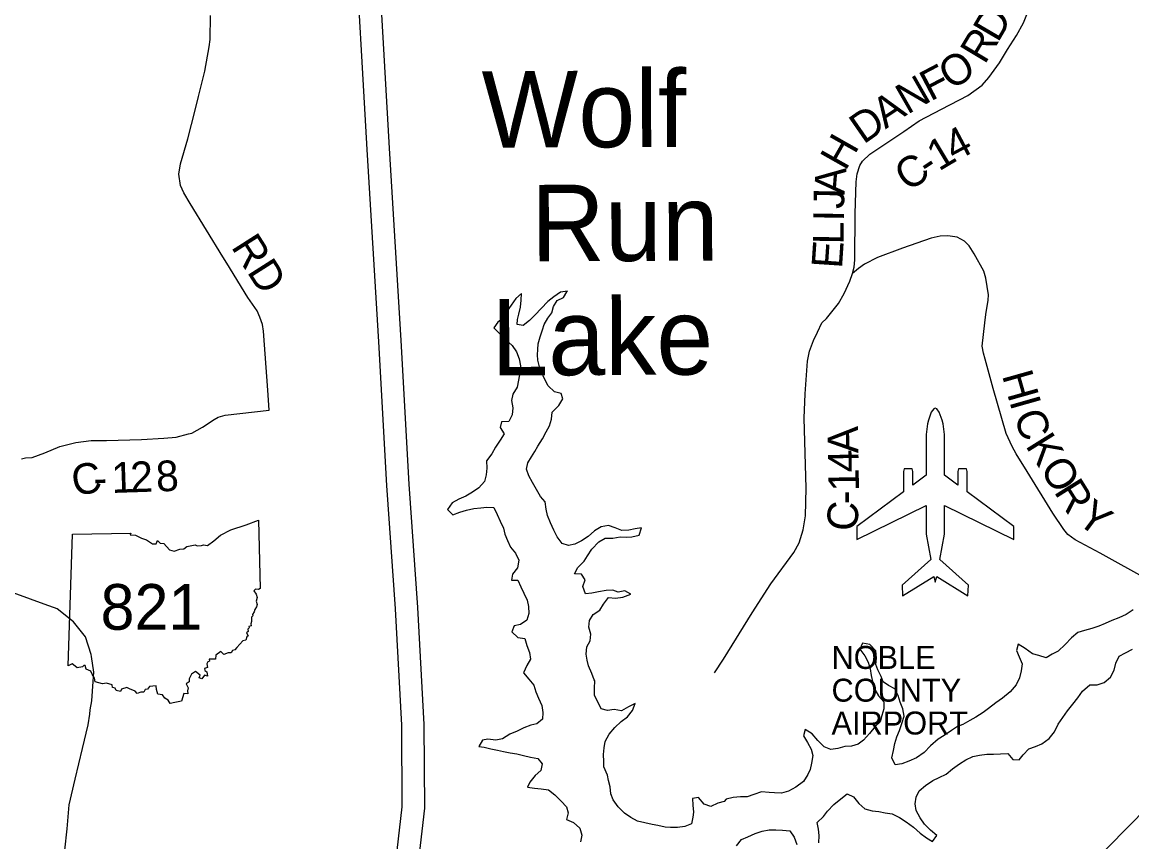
# Model space of a CAD drawing. Extents: x -452339 to 6403467, y -1 to 1814750.
# Drawn here: x -60980 to -50105, y 1606675 to 1614709 of the extents above; entities that cross this region are included whole.
import ezdxf

# ---------------------------------------------------------------- set-up
doc = ezdxf.new("R2010")
doc.units = 0
for name, color, linetype in [('Default', 7, 'Continuous'), ('GM_X_Adjacent_County_Text', 7, 'Continuous'), ('GM_X_County', 7, 'Continuous'), ('GM_X_County_Road', 7, 'Continuous'), ('GM_X_Minor_Lake_Text', 7, 'Continuous')]:
    doc.layers.add(name, color=color, linetype=linetype)

msp = doc.modelspace()

# ---------------------------------------------------------------- linework, layer by layer
at = {"layer": 'Default'}
msp.add_line((-60528, 1608400), (-60486, 1609691), dxfattribs=at)
for points in [[(-58975, 1612346), (-59013, 1612409), (-59335, 1612931), (-59395, 1613037), (-59427, 1613109), (-59443, 1613218), (-59427, 1613320), (-59356, 1613566), (-59285, 1613847), (-59252, 1613979), (-59190, 1614228), (-59147, 1614466), (-59139, 1614540), (-59135, 1614773)], [(-52843, 1612244), (-52825, 1612306), (-52819, 1612378), (-52817, 1612833), (-52808, 1613145), (-52796, 1613221), (-52770, 1613304), (-52744, 1613348), (-52672, 1613416), (-52340, 1613637), (-52188, 1613743), (-51971, 1613856), (-51713, 1613990), (-51573, 1614091), (-51505, 1614165), (-51401, 1614310), (-51325, 1614440), (-51235, 1614578), (-51168, 1614701), (-51134, 1614783)], [(-49939, 1609241), (-50417, 1609504), (-50659, 1609634), (-50733, 1609688), (-50773, 1609736), (-50879, 1609898), (-51131, 1610305), (-51237, 1610479), (-51279, 1610551), (-51338, 1610677), (-51464, 1611118), (-51542, 1611406), (-51558, 1611464), (-51572, 1611534), (-51547, 1611763), (-51537, 1611843), (-51513, 1611983), (-51509, 1612035), (-51535, 1612201), (-51557, 1612268), (-51649, 1612438), (-51699, 1612518), (-51745, 1612562), (-51817, 1612602), (-51907, 1612616), (-51985, 1612612), (-52073, 1612593), (-52351, 1612495), (-52599, 1612402), (-52725, 1612336), (-52783, 1612294), (-52843, 1612244)], [(-58560, 1610905), (-58572, 1611101), (-58616, 1611680), (-58626, 1611746), (-58652, 1611818), (-58678, 1611880), (-58768, 1612011), (-58975, 1612346)], [(-54196, 1608333), (-54107, 1608466), (-53827, 1608919), (-53643, 1609203), (-53418, 1609510), (-53366, 1609606), (-53326, 1609733), (-53302, 1609869), (-53298, 1610143), (-53317, 1610828), (-53307, 1611067), (-53284, 1611387), (-53264, 1611484), (-53224, 1611588), (-53184, 1611672), (-53142, 1611762), (-53098, 1611804), (-53044, 1611871), (-52980, 1611951), (-52924, 1612049), (-52869, 1612171), (-52843, 1612244)], [(-60986, 1610429), (-60946, 1610439), (-60882, 1610443), (-60758, 1610489), (-60611, 1610549), (-60453, 1610590), (-60305, 1610608), (-60155, 1610608), (-59809, 1610617), (-59591, 1610631), (-59471, 1610643), (-59351, 1610673), (-59318, 1610680), (-59213, 1610740), (-59099, 1610814), (-59059, 1610836), (-58989, 1610858), (-58560, 1610905)], [(-60486, 1609691), (-59914, 1609700), (-59922, 1609684), (-59869, 1609681), (-59811, 1609653), (-59763, 1609636), (-59704, 1609595), (-59668, 1609595), (-59653, 1609629), (-59626, 1609603), (-59593, 1609598), (-59537, 1609536), (-59491, 1609523), (-59436, 1609544), (-59395, 1609548), (-59365, 1609569), (-59286, 1609587), (-59264, 1609576), (-59223, 1609578), (-59202, 1609586), (-59165, 1609579), (-59102, 1609626), (-59036, 1609681), (-58935, 1609734), (-58784, 1609783), (-58664, 1609827), (-58647, 1609157)], [(-60663, 1608968), (-60729, 1608992), (-61068, 1609116)], [(-58647, 1609157), (-58665, 1609148), (-58692, 1609152), (-58711, 1609134), (-58688, 1609102), (-58677, 1609069), (-58687, 1609033), (-58677, 1609002), (-58683, 1608977), (-58701, 1608952), (-58707, 1608928), (-58721, 1608903), (-58720, 1608889), (-58734, 1608878), (-58732, 1608836), (-58739, 1608813), (-58736, 1608793), (-58759, 1608787), (-58754, 1608771), (-58768, 1608758), (-58765, 1608736), (-58782, 1608722), (-58766, 1608694), (-58778, 1608685), (-58789, 1608651), (-58818, 1608644), (-58876, 1608581), (-58897, 1608558), (-58920, 1608552), (-58933, 1608527), (-58961, 1608527), (-59004, 1608511), (-59032, 1608539), (-59081, 1608505), (-59086, 1608464), (-59147, 1608466), (-59145, 1608445), (-59159, 1608439), (-59171, 1608419), (-59164, 1608383), (-59193, 1608373), (-59190, 1608353), (-59171, 1608340), (-59163, 1608300), (-59194, 1608308), (-59218, 1608274), (-59245, 1608282), (-59236, 1608310), (-59280, 1608345), (-59321, 1608317), (-59342, 1608273), (-59343, 1608243), (-59374, 1608225), (-59354, 1608183), (-59358, 1608154), (-59357, 1608127), (-59395, 1608128), (-59419, 1608054)], [(-60318, 1607927), (-60312, 1607968), (-60298, 1608057), (-60283, 1608245), (-60279, 1608337), (-60301, 1608491), (-60304, 1608512), (-60359, 1608686), (-60478, 1608832), (-60638, 1608959), (-60663, 1608968)], [(-50092, 1608948), (-50162, 1608903), (-50231, 1608872), (-50301, 1608845), (-50365, 1608815), (-50428, 1608790), (-50498, 1608767), (-50568, 1608746), (-50634, 1608728), (-50697, 1608675), (-50760, 1608610), (-50826, 1608545), (-50887, 1608515), (-50945, 1608478), (-51015, 1608501), (-51079, 1608519), (-51150, 1608570), (-51218, 1608611), (-51236, 1608549), (-51209, 1608487), (-51180, 1608421), (-51190, 1608351), (-51207, 1608281), (-51238, 1608213), (-51299, 1608146), (-51371, 1608083), (-51438, 1608038), (-51510, 1607981), (-51561, 1607943), (-51635, 1607896), (-51694, 1607863), (-51762, 1607826), (-51814, 1607804), (-51871, 1607767), (-51945, 1607716), (-52002, 1607680), (-52078, 1607615), (-52139, 1607552), (-52216, 1607499), (-52290, 1607466), (-52360, 1607438), (-52424, 1607431), (-52456, 1607499), (-52441, 1607571), (-52428, 1607639), (-52409, 1607705), (-52383, 1607766), (-52358, 1607836), (-52335, 1607906)], [(-59419, 1608054), (-59485, 1608040), (-59531, 1608031), (-59548, 1608065), (-59581, 1608083), (-59603, 1608116), (-59650, 1608121), (-59662, 1608168), (-59667, 1608205), (-59732, 1608196), (-59750, 1608173), (-59773, 1608167), (-59786, 1608143), (-59818, 1608142), (-59852, 1608130), (-59874, 1608153), (-59929, 1608176), (-59954, 1608188), (-60006, 1608170), (-60017, 1608148), (-60058, 1608158), (-60068, 1608182), (-60093, 1608189), (-60099, 1608215), (-60152, 1608229), (-60194, 1608223), (-60266, 1608244), (-60270, 1608278), (-60295, 1608319), (-60307, 1608348), (-60353, 1608369), (-60362, 1608403), (-60377, 1608402), (-60390, 1608389), (-60441, 1608382), (-60461, 1608396), (-60490, 1608420), (-60528, 1608400)], [(-60573, 1606300), (-60561, 1606593), (-60538, 1606802), (-60519, 1607037), (-60460, 1607290), (-60389, 1607589), (-60333, 1607822), (-60318, 1607927)], [(-56900, 1601787), (-56832, 1601823), (-56536, 1601971), (-56496, 1601992), (-56117, 1602200), (-55807, 1602369), (-55583, 1602550), (-54899, 1603355), (-54089, 1604287), (-53837, 1604520), (-53472, 1604763), (-53184, 1604921), (-53155, 1604931), (-52573, 1605151), (-52123, 1605283), (-51847, 1605384), (-51593, 1605470), (-51435, 1605571), (-50876, 1606075), (-50152, 1606812), (-49304, 1607670)]]:
    msp.add_lwpolyline(points, dxfattribs=at)
msp.add_lwpolyline([(-52344, 1610104), (-52800, 1609767), (-52800, 1609637), (-52121, 1609972), (-52121, 1609690), (-52076, 1609441), (-52355, 1609190), (-52351, 1609087), (-52045, 1609277), (-52031, 1609221), (-52017, 1609277), (-51711, 1609087), (-51706, 1609190), (-51986, 1609441), (-51941, 1609690), (-51941, 1609972), (-51262, 1609637), (-51262, 1609767), (-51718, 1610104), (-51718, 1610306), (-51725, 1610330), (-51803, 1610330), (-51810, 1610306), (-51810, 1610172), (-51941, 1610269), (-51941, 1610269), (-51941, 1610667), (-51954, 1610772), (-51965, 1610809), (-51992, 1610886), (-52016, 1610920), (-52031, 1610926), (-52045, 1610920), (-52070, 1610886), (-52097, 1610809), (-52108, 1610772), (-52121, 1610667), (-52121, 1610269), (-52252, 1610172), (-52252, 1610306), (-52259, 1610330), (-52336, 1610330), (-52344, 1610306)], close=True, dxfattribs=at)
at = {"layer": 'GM_X_County_Road'}
for points in [[(-58024, 1603953), (-57930, 1604177), (-57705, 1604759), (-57647, 1604920), (-57363, 1605645), (-57337, 1605728), (-57219, 1606057), (-57156, 1606262), (-57087, 1606553), (-57035, 1607005), (-57040, 1607824), (-57101, 1608973), (-57187, 1610182), (-57265, 1611589), (-57379, 1613474), (-57506, 1615703)], [(-58227, 1604038), (-58134, 1604259), (-57911, 1604836), (-57853, 1604997), (-57571, 1605717), (-57546, 1605798), (-57428, 1606127), (-57368, 1606320), (-57304, 1606591), (-57255, 1607017), (-57260, 1607818), (-57320, 1608959), (-57407, 1610168), (-57485, 1611576), (-57598, 1613461), (-57725, 1615691)]]:
    msp.add_lwpolyline(points, dxfattribs=at)
at = {"layer": 'GM_X_Minor_Lake_Text'}
for points in [[(-55637, 1612072), (-55704, 1612061), (-55768, 1612016), (-55829, 1611971), (-55895, 1611903), (-55952, 1611842), (-56009, 1611785), (-56069, 1611736), (-56129, 1611746), (-56124, 1611796), (-56114, 1611846), (-56097, 1611914), (-56091, 1611983), (-56088, 1612049), (-56142, 1612000), (-56189, 1611935), (-56228, 1611881), (-56256, 1611813), (-56319, 1611770), (-56359, 1611713), (-56239, 1611596), (-56179, 1611541), (-56134, 1611477), (-56110, 1611410), (-56097, 1611342), (-56104, 1611273), (-56117, 1611201), (-56129, 1611133), (-56172, 1611064), (-56185, 1611000), (-56171, 1610930), (-56178, 1610860), (-56211, 1610794), (-56283, 1610791), (-56295, 1610735), (-56256, 1610675), (-56297, 1610611), (-56341, 1610544), (-56378, 1610479), (-56431, 1610411), (-56426, 1610339), (-56432, 1610271), (-56449, 1610206), (-56506, 1610144), (-56566, 1610101), (-56633, 1610062), (-56701, 1610033), (-56765, 1609999), (-56810, 1609934), (-56758, 1609881), (-56690, 1609905), (-56624, 1609926), (-56554, 1609943), (-56486, 1609948), (-56426, 1609956), (-56358, 1609951), (-56324, 1609883), (-56295, 1609818), (-56264, 1609748), (-56250, 1609692), (-56225, 1609628), (-56194, 1609562), (-56144, 1609505), (-56113, 1609437), (-56124, 1609361), (-56174, 1609298), (-56183, 1609240), (-56123, 1609239), (-56092, 1609175), (-56064, 1609111), (-56031, 1609044), (-56019, 1608982), (-56016, 1608914), (-56035, 1608847), (-56097, 1608805), (-56158, 1608792), (-56182, 1608732), (-56121, 1608678), (-56053, 1608667), (-56033, 1608599), (-56008, 1608531), (-55997, 1608465), (-56033, 1608403), (-56066, 1608330), (-56013, 1608269), (-55965, 1608211), (-55946, 1608145), (-55921, 1608082), (-55887, 1608012), (-55878, 1607942), (-55881, 1607878), (-55935, 1607831), (-55994, 1607817), (-56062, 1607792), (-56128, 1607759), (-56200, 1607732), (-56273, 1607685), (-56337, 1607671), (-56415, 1607680), (-56467, 1607671), (-56506, 1607611)], [(-55369, 1608252), (-55375, 1608262), (-55396, 1608326), (-55429, 1608399), (-55443, 1608455), (-55454, 1608515), (-55445, 1608585), (-55413, 1608646), (-55408, 1608712), (-55425, 1608778), (-55419, 1608844), (-55384, 1608904), (-55320, 1608945), (-55283, 1609006), (-55234, 1609070), (-55164, 1609063), (-55094, 1609072), (-55014, 1609101), (-55074, 1609134), (-55140, 1609121), (-55190, 1609141), (-55258, 1609138), (-55332, 1609127), (-55398, 1609112), (-55460, 1609106), (-55485, 1609178), (-55463, 1609244), (-55498, 1609298), (-55566, 1609301), (-55533, 1609365), (-55473, 1609426), (-55440, 1609478), (-55398, 1609543), (-55329, 1609614), (-55266, 1609653), (-55192, 1609653), (-55120, 1609664), (-55056, 1609661), (-55004, 1609663), (-54932, 1609682), (-54911, 1609753), (-54973, 1609742), (-55033, 1609731), (-55102, 1609728), (-55169, 1609754), (-55233, 1609775), (-55307, 1609762), (-55370, 1609724), (-55434, 1609669), (-55499, 1609626), (-55563, 1609593), (-55627, 1609581), (-55687, 1609600), (-55738, 1609665), (-55770, 1609729), (-55803, 1609801), (-55830, 1609875), (-55846, 1609937), (-55855, 1610009), (-55900, 1610060), (-55938, 1610128), (-55979, 1610197), (-56016, 1610263), (-56036, 1610329), (-56025, 1610391), (-55990, 1610448), (-55956, 1610500), (-55927, 1610552), (-55880, 1610625), (-55844, 1610694), (-55811, 1610754), (-55794, 1610818), (-55786, 1610886), (-55719, 1610951), (-55682, 1611016), (-55698, 1611070), (-55764, 1611087), (-55825, 1611144), (-55862, 1611212), (-55890, 1611278), (-55911, 1611332), (-55925, 1611396), (-55928, 1611448), (-55927, 1611500), (-55923, 1611556), (-55904, 1611624), (-55879, 1611692), (-55865, 1611745), (-55828, 1611809), (-55788, 1611860), (-55773, 1611922), (-55738, 1611980), (-55674, 1612011), (-55642, 1612066), (-55637, 1612072)], [(-50092, 1608948), (-50162, 1608903), (-50231, 1608872), (-50301, 1608845), (-50365, 1608815), (-50428, 1608790), (-50498, 1608767), (-50568, 1608746), (-50634, 1608728), (-50697, 1608675), (-50760, 1608610), (-50826, 1608545), (-50887, 1608515), (-50945, 1608478), (-51015, 1608501), (-51079, 1608519), (-51150, 1608570), (-51218, 1608611), (-51236, 1608549), (-51209, 1608487), (-51180, 1608421), (-51190, 1608351), (-51207, 1608281), (-51238, 1608213), (-51299, 1608146), (-51371, 1608083), (-51438, 1608038), (-51510, 1607981), (-51561, 1607943), (-51635, 1607896), (-51694, 1607863), (-51762, 1607826), (-51814, 1607804), (-51871, 1607767), (-51945, 1607716), (-52002, 1607680), (-52078, 1607615), (-52139, 1607552), (-52216, 1607499), (-52290, 1607466), (-52360, 1607438), (-52424, 1607431), (-52456, 1607499), (-52441, 1607571), (-52428, 1607639), (-52409, 1607705), (-52383, 1607766), (-52358, 1607836), (-52335, 1607906)], [(-52335, 1607906), (-52349, 1607978), (-52376, 1608044), (-52395, 1608108), (-52429, 1608174), (-52490, 1608209), (-52542, 1608244), (-52561, 1608296), (-52595, 1608360), (-52614, 1608414), (-52606, 1608474), (-52613, 1608546), (-52672, 1608609), (-52744, 1608623), (-52771, 1608564), (-52723, 1608497), (-52690, 1608435), (-52671, 1608371), (-52659, 1608305), (-52644, 1608235), (-52625, 1608167), (-52587, 1608106), (-52534, 1608046), (-52537, 1607980), (-52555, 1607912), (-52570, 1607850), (-52621, 1607805), (-52675, 1607738), (-52734, 1607670), (-52786, 1607631), (-52851, 1607612), (-52917, 1607608), (-52987, 1607591), (-53055, 1607580), (-53121, 1607606), (-53182, 1607669), (-53239, 1607734), (-53307, 1607776), (-53324, 1607713), (-53284, 1607648), (-53249, 1607584), (-53230, 1607520), (-53246, 1607446), (-53259, 1607384), (-53280, 1607334), (-53322, 1607265), (-53397, 1607210), (-53469, 1607173), (-53540, 1607153), (-53608, 1607154), (-53660, 1607159), (-53733, 1607166), (-53810, 1607138), (-53874, 1607115), (-53940, 1607116), (-54012, 1607111), (-54080, 1607093)], [(-53172, 1606666), (-53168, 1606738), (-53177, 1606798), (-53188, 1606866), (-53126, 1606925), (-53089, 1606975), (-53025, 1607040), (-52956, 1607097), (-52895, 1607145), (-52832, 1607116), (-52782, 1607051), (-52723, 1606999), (-52651, 1606980), (-52585, 1606973), (-52523, 1606959), (-52453, 1606948), (-52382, 1606915), (-52316, 1606871), (-52245, 1606820), (-52181, 1606761), (-52118, 1606713), (-52058, 1606680), (-52017, 1606737), (-52079, 1606788), (-52136, 1606847), (-52180, 1606911), (-52219, 1606981), (-52230, 1607049), (-52218, 1607113), (-52189, 1607175), (-52126, 1607228), (-52056, 1607275), (-51993, 1607305), (-51925, 1607338), (-51861, 1607389), (-51794, 1607438), (-51732, 1607478), (-51663, 1607511), (-51599, 1607524), (-51527, 1607533), (-51461, 1607535), (-51391, 1607538), (-51319, 1607541), (-51271, 1607483), (-51209, 1607478), (-51169, 1607529), (-51116, 1607587), (-51050, 1607610), (-50988, 1607637), (-50915, 1607688), (-50864, 1607754), (-50826, 1607827), (-50781, 1607895), (-50736, 1607958), (-50684, 1608024), (-50635, 1608085), (-50590, 1608152), (-50518, 1608214), (-50446, 1608215), (-50375, 1608238), (-50315, 1608289), (-50278, 1608359), (-50261, 1608427), (-50229, 1608496), (-50168, 1608529), (-50098, 1608563)], [(-54080, 1607093), (-54101, 1607072), (-54161, 1607054), (-54231, 1607021), (-54295, 1607044), (-54352, 1607108), (-54412, 1607101), (-54407, 1607033), (-54402, 1606967), (-54406, 1606917), (-54421, 1606853), (-54485, 1606826), (-54557, 1606815), (-54625, 1606816), (-54679, 1606820), (-54751, 1606835), (-54805, 1606846), (-54879, 1606860), (-54949, 1606877), (-55014, 1606914), (-55078, 1606956), (-55139, 1607019), (-55187, 1607087), (-55212, 1607146), (-55219, 1607214), (-55233, 1607276), (-55244, 1607330), (-55279, 1607410), (-55279, 1607464), (-55282, 1607532), (-55276, 1607596), (-55267, 1607660), (-55228, 1607729), (-55173, 1607795), (-55109, 1607856), (-55048, 1607901), (-55000, 1607962), (-54971, 1608030), (-55039, 1607997), (-55108, 1607960), (-55178, 1607972), (-55242, 1607963), (-55306, 1607978), (-55339, 1608046), (-55372, 1608110), (-55372, 1608180), (-55369, 1608252)], [(-56506, 1607611), (-56452, 1607603), (-56386, 1607588), (-56322, 1607573), (-56262, 1607561), (-56198, 1607546), (-56132, 1607539), (-56067, 1607521), (-55997, 1607506), (-55925, 1607493), (-55883, 1607441), (-55898, 1607375), (-55953, 1607325), (-56005, 1607260), (-56026, 1607210), (-55958, 1607202), (-55894, 1607193), (-55822, 1607184), (-55760, 1607136), (-55697, 1607075), (-55644, 1607018), (-55630, 1606958), (-55647, 1606895), (-55577, 1606866), (-55516, 1606809), (-55494, 1606741), (-55509, 1606675)], [(-53981, 1606637), (-53932, 1606698), (-53868, 1606723), (-53798, 1606757), (-53729, 1606780), (-53659, 1606793), (-53595, 1606794), (-53527, 1606790), (-53457, 1606783), (-53414, 1606721), (-53387, 1606648)]]:
    msp.add_lwpolyline(points, dxfattribs=at)

# ---------------------------------------------------------------- texts
at = {"layer": 'Default'}
msp.add_text('821', height=447.7, dxfattribs=at).set_placement((-60212, 1608754))
for s, p in [('NOBLE', (-53048, 1608370)), ('COUNTY', (-53048, 1608049)), ('AIRPORT', (-53048, 1607727))]:
    msp.add_text(s, height=225, rotation=0, dxfattribs=at).set_placement(p)
at = {"layer": 'GM_X_Adjacent_County_Text'}
for s, p in [('Wolf', (-56475, 1613478)), ('Run', (-55992, 1612364)), ('Lake', (-56381, 1611246))]:
    msp.add_text(s, height=750, rotation=0.2496, dxfattribs=at).set_placement(p)
at = {"layer": 'GM_X_County'}
for s, rotation, p in [('D', 59.6092, (-51418, 1614501)), ('R', 58.9422, (-51547, 1614286)), ('O', 32.4395, (-51875, 1614037)), ('F', 27.6382, (-52078, 1613930)), ('N', 29.7336, (-52305, 1613800)), ('A', 33.7143, (-52520, 1613657)), ('D', 34.7974, (-52735, 1613507)), ('4', 28.1013, (-51841, 1613336)), ('H', 60.4932, (-52912, 1613243)), ('1', 30.9468, (-51996, 1613243)), ('C', 33.7788, (-52300, 1613041)), ('-', 33.2614, (-52096, 1613177)), ('A', 85.5001, (-52922, 1613013)), ('J', 88.9276, (-52925, 1612877)), ('I', 89.0008, (-52927, 1612754)), ('L', 89.0684, (-52931, 1612529)), ('RD', 302.5098, (-58938, 1612507)), ('E', 86.1745, (-52946, 1612289)), ('H', 285.7638, (-51379, 1611248)), ('I', 285.8691, (-51307, 1610994)), ('C', 289.8281, (-51267, 1610854)), ('A', 91.1547, (-52784, 1610484)), ('K', 302.0071, (-51153, 1610559)), ('4', 91.0325, (-52781, 1610299)), ('C', 9.2948, (-60470, 1610064)), ('1', 1.9414, (-60100, 1610094)), ('2', 1.9462, (-59916, 1610100)), ('8', 2.8385, (-59662, 1610107)), ('O', 301.4386, (-51013, 1610336)), ('1', 90.6734, (-52779, 1610112)), ('-', 2.1939, (-60277, 1610090)), ('R', 302.0772, (-50874, 1610108)), ('-', 89.7324, (-52779, 1609983)), ('Y', 323.1999, (-50661, 1609811)), ('C', 85.1586, (-52801, 1609712))]:
    msp.add_text(s, height=300, rotation=rotation, dxfattribs=at).set_placement(p)

doc.saveas('drawing.dxf')
